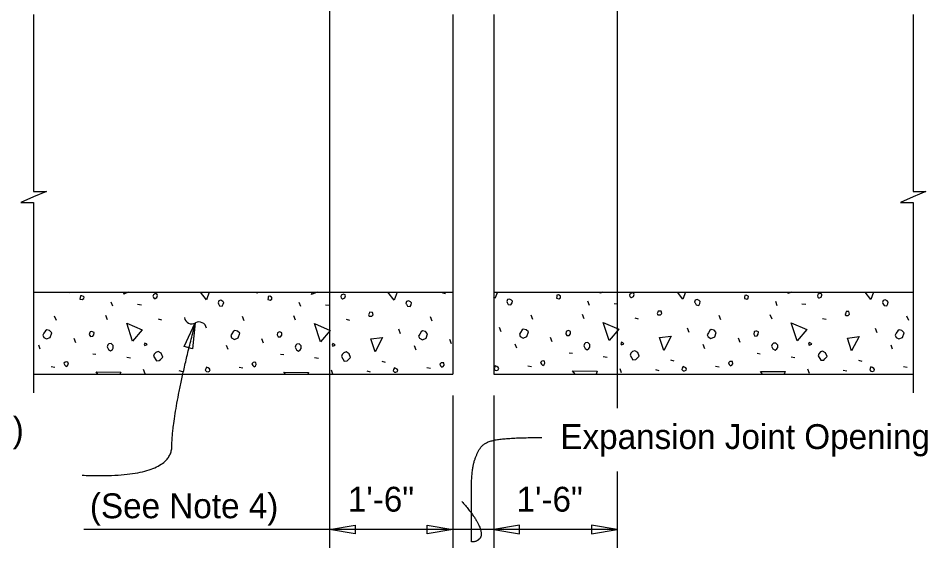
# Model space of a CAD drawing. Extents: x 0 to 41.1, y 0 to 25.9.
# Drawn here: x 23.59 to 30.96, y 12.63 to 16.93 of the extents above; entities that cross this region are included whole.
import ezdxf

# ---------------------------------------------------------------- set-up
doc = ezdxf.new("R2010")
doc.units = 0
for name, color, linetype in [('CL_Major', 7, 'Continuous'), ('Dimension', 7, 'Continuous'), ('Miscellaneous', 7, 'Continuous'), ('SupstrConc', 7, 'Continuous'), ('TextStructures', 7, 'Continuous')]:
    doc.layers.add(name, color=color, linetype=linetype)

msp = doc.modelspace()

# ---------------------------------------------------------------- linework, layer by layer
at = {"layer": 'CL_Major'}
for p, q in [((26.1118, 25.3255), (26.1118, 12.6331)), ((28.4451, 25.3255), (28.4451, 13.7657)), ((28.4451, 13.2526), (28.4451, 12.6331))]:
    msp.add_line(p, q, dxfattribs=at)
at = {"layer": 'Dimension'}
for p, q in [((27.1118, 13.8672), (27.1118, 12.6331)), ((27.4452, 13.8672), (27.4452, 12.6331)), ((28.4451, 12.7811), (26.1118, 12.7811))]:
    msp.add_line(p, q, dxfattribs=at)
for points in [[(23.712, 16.9573), (23.712, 15.5233), (23.8153, 15.5233), (23.712, 15.4783), (23.6086, 15.4333), (23.712, 15.4333), (23.712, 13.8908)], [(30.845, 16.9573), (30.845, 15.5233), (30.9484, 15.5233), (30.845, 15.4783), (30.7417, 15.4333), (30.845, 15.4333), (30.845, 13.8908)]]:
    msp.add_lwpolyline(points, dxfattribs=at)
for points in [[(25.0235, 14.4569), (25.0013, 14.2468), (24.9333, 14.2659)], [(26.1118, 12.7812), (26.3201, 12.8165), (26.3201, 12.746)], [(27.1118, 12.7812), (26.9036, 12.746), (26.9036, 12.8165)], [(27.4452, 12.7812), (27.6534, 12.746), (27.6534, 12.8165)], [(28.4452, 12.7812), (28.2369, 12.8165), (28.2369, 12.746)]]:
    msp.add_lwpolyline(points, close=True, dxfattribs=at)
for centre, start, end in [((24.9944, 14.508), 188.42943, 300.15665), ((25.0543, 14.4049), 8.42943, 120.15665)]:
    msp.add_arc(centre, 0.0596, start, end, dxfattribs=at)
for points in [[(24.107, 13.2213), (24.8329, 13.1916), (24.8345, 13.7279), (25.0236, 14.4567)], [(27.1848, 13.0096), (27.3029, 12.8733), (27.3543, 12.734), (27.3059, 12.6826), (27.2628, 12.6826), (27.2628, 12.6826), (27.2628, 12.9339), (27.2628, 13.2367), (27.2938, 13.373), (27.3664, 13.4972), (27.5995, 13.5274), (27.8326, 13.5274)]]:
    msp.add_open_spline(points, degree=2, dxfattribs=at)
at = {"layer": 'Miscellaneous'}
for p, q in [((23.9875, 14.7072), (24.0062, 14.7035)), ((25.5035, 14.7053), (25.53, 14.7)), ((27.0273, 14.7017), (27.0539, 14.6964)), ((29.3939, 14.7072), (29.395, 14.707)), ((24.3545, 14.5921), (24.3421, 14.6257)), ((24.5542, 14.608), (24.5861, 14.6045)), ((25.8783, 14.5886), (25.8659, 14.6222)), ((28.2194, 14.5992), (28.2071, 14.6328)), ((28.4192, 14.6151), (28.451, 14.6116)), ((29.7432, 14.5957), (29.7309, 14.6292)), ((29.943, 14.6116), (29.9748, 14.608)), ((26.0781, 14.6045), (26.1099, 14.601)), ((23.8966, 14.4772), (23.8825, 14.5126)), ((24.3121, 14.4825), (24.2979, 14.5179)), ((24.7222, 14.4896), (24.7505, 14.4825)), ((25.4204, 14.4737), (25.4063, 14.509)), ((25.8359, 14.479), (25.8217, 14.5143)), ((26.246, 14.4861), (26.2743, 14.479)), ((26.9443, 14.4701), (26.9301, 14.5055)), ((27.7616, 14.4843), (27.7474, 14.5196)), ((28.177, 14.4896), (28.1629, 14.5249)), ((28.5871, 14.4967), (28.6154, 14.4896)), ((29.2854, 14.4807), (29.2713, 14.5161)), ((29.7008, 14.4861), (29.6867, 14.5214)), ((30.1109, 14.4931), (30.1392, 14.4861)), ((30.8092, 14.4772), (30.7951, 14.5126)), ((26.6879, 14.3694), (26.6738, 14.4047)), ((27.5053, 14.3835), (27.4911, 14.4189)), ((29.0291, 14.38), (29.0149, 14.4153)), ((30.5529, 14.3765), (30.5387, 14.4118)), ((24.054, 14.2951), (24.0398, 14.3305)), ((25.5778, 14.2916), (25.5636, 14.327)), ((27.1016, 14.2881), (27.0874, 14.3234)), ((27.9189, 14.3022), (27.9048, 14.3376)), ((29.4427, 14.2987), (29.4286, 14.334)), ((23.7658, 14.2439), (23.7534, 14.2775)), ((25.2896, 14.2403), (25.2773, 14.2739)), ((26.8134, 14.2368), (26.8011, 14.2704)), ((27.6308, 14.2509), (27.6184, 14.2845)), ((29.1546, 14.2474), (29.1422, 14.281)), ((30.6784, 14.2439), (30.666, 14.2775)), ((24.1918, 14.2067), (24.2166, 14.2032)), ((24.4676, 14.1785), (24.4977, 14.1732)), ((25.7157, 14.2032), (25.7404, 14.1997)), ((25.9914, 14.1749), (26.0215, 14.1696)), ((28.0568, 14.2138), (28.0815, 14.2103)), ((28.3326, 14.1855), (28.3626, 14.1802)), ((29.5806, 14.2103), (29.6054, 14.2067)), ((29.8564, 14.182), (29.8864, 14.1767)), ((23.8542, 14.1024), (23.8843, 14.0971)), ((25.378, 14.0989), (25.4081, 14.0936)), ((26.5359, 14.1466), (26.5642, 14.1396)), ((26.9018, 14.0954), (26.9319, 14.0901)), ((27.7192, 14.1095), (27.7492, 14.1042)), ((28.877, 14.1572), (28.9053, 14.1502)), ((29.243, 14.106), (29.273, 14.1007)), ((30.4009, 14.1537), (30.4291, 14.1466)), ((30.7668, 14.1024), (30.7968, 14.0971)), ((24.6161, 14.0441), (24.6037, 14.0777)), ((24.8901, 14.0706), (24.9184, 14.0636)), ((26.1399, 14.0406), (26.1275, 14.0742)), ((26.4139, 14.0671), (26.4422, 14.06)), ((28.4811, 14.0512), (28.4687, 14.0848)), ((28.7551, 14.0777), (28.7833, 14.0706)), ((30.0049, 14.0476), (29.9925, 14.0812)), ((30.2789, 14.0742), (30.3072, 14.0671))]:
    msp.add_line(p, q, dxfattribs=at)
for points in [[(24.4429, 14.6911), (24.4478, 14.7072)], [(24.4788, 14.7072), (24.4429, 14.6911)], [(24.6904, 14.6558), (24.6974, 14.6558), (24.7116, 14.6628), (24.7169, 14.6787), (24.7151, 14.6876), (24.701, 14.6946), (24.6833, 14.684), (24.6797, 14.6734), (24.6833, 14.6628), (24.6904, 14.6558)], [(25.1129, 14.6434), (25.0643, 14.7072)], [(25.1367, 14.7072), (25.1129, 14.6434)], [(25.9667, 14.6876), (25.9727, 14.7072)], [(26.0105, 14.7072), (25.9667, 14.6876)], [(26.2142, 14.6522), (26.2212, 14.6522), (26.2354, 14.6593), (26.2407, 14.6752), (26.2389, 14.684), (26.2248, 14.6911), (26.2071, 14.6805), (26.2036, 14.6699), (26.2071, 14.6593), (26.2142, 14.6522)], [(26.6367, 14.6398), (26.5854, 14.7072)], [(26.6619, 14.7072), (26.6367, 14.6398)], [(27.4739, 14.7072), (27.454, 14.654)], [(27.9525, 14.6575), (27.9719, 14.6522), (27.9843, 14.6611), (27.9861, 14.6734), (27.9826, 14.677), (27.9684, 14.684), (27.956, 14.6823), (27.9543, 14.6699), (27.9525, 14.6575)], [(28.3078, 14.6982), (28.3106, 14.7072)], [(28.328, 14.7072), (28.3078, 14.6982)], [(28.5553, 14.6628), (28.5624, 14.6628), (28.5765, 14.6699), (28.5818, 14.6858), (28.5801, 14.6946), (28.5659, 14.7017), (28.5482, 14.6911), (28.5447, 14.6805), (28.5482, 14.6699), (28.5553, 14.6628)], [(28.9778, 14.6505), (28.9346, 14.7072)], [(28.999, 14.7072), (28.9778, 14.6505)], [(29.8316, 14.6946), (29.8355, 14.7072)], [(29.8597, 14.7072), (29.8316, 14.6946)], [(30.0791, 14.6593), (30.0862, 14.6593), (30.1003, 14.6664), (30.1056, 14.6823), (30.1039, 14.6911), (30.0897, 14.6982), (30.0721, 14.6876), (30.0685, 14.677), (30.0721, 14.6664), (30.0791, 14.6593)], [(30.5016, 14.6469), (30.4558, 14.7072)], [(30.5242, 14.7072), (30.5016, 14.6469)], [(24.0875, 14.6505), (24.107, 14.6452), (24.1194, 14.654), (24.1211, 14.6664), (24.1176, 14.6699), (24.1035, 14.677), (24.0911, 14.6752), (24.0893, 14.6628), (24.0875, 14.6505)], [(25.2118, 14.6116), (25.2207, 14.5957), (25.2419, 14.5921), (25.2507, 14.608), (25.2543, 14.6222), (25.2454, 14.631), (25.2295, 14.6398), (25.2136, 14.6345), (25.2083, 14.6186), (25.2118, 14.6116)], [(25.6114, 14.6469), (25.6308, 14.6416), (25.6432, 14.6505), (25.6449, 14.6628), (25.6414, 14.6664), (25.6273, 14.6734), (25.6149, 14.6717), (25.6131, 14.6593), (25.6114, 14.6469)], [(26.7357, 14.608), (26.7445, 14.5921), (26.7657, 14.5886), (26.7746, 14.6045), (26.7781, 14.6186), (26.7692, 14.6275), (26.7533, 14.6363), (26.7374, 14.631), (26.7321, 14.6151), (26.7357, 14.608)], [(27.454, 14.654), (27.4451, 14.6656)], [(27.553, 14.6222), (27.5618, 14.6063), (27.583, 14.6027), (27.5919, 14.6186), (27.5954, 14.6328), (27.5866, 14.6416), (27.5707, 14.6505), (27.5548, 14.6452), (27.5494, 14.6292), (27.553, 14.6222)], [(29.0768, 14.6186), (29.0856, 14.6027), (29.1069, 14.5992), (29.1157, 14.6151), (29.1192, 14.6292), (29.1104, 14.6381), (29.0945, 14.6469), (29.0786, 14.6416), (29.0733, 14.6257), (29.0768, 14.6186)], [(29.4763, 14.654), (29.4958, 14.6487), (29.5081, 14.6575), (29.5099, 14.6699), (29.5064, 14.6734), (29.4922, 14.6805), (29.4798, 14.6787), (29.4781, 14.6664), (29.4763, 14.654)], [(30.6006, 14.6151), (30.6095, 14.5992), (30.6307, 14.5957), (30.6395, 14.6116), (30.643, 14.6257), (30.6342, 14.6345), (30.6183, 14.6434), (30.6024, 14.6381), (30.5971, 14.6222), (30.6006, 14.6151)], [(26.4334, 14.5108), (26.4546, 14.5108), (26.4652, 14.5214), (26.4599, 14.5409), (26.4369, 14.5426), (26.4334, 14.532), (26.4281, 14.5232), (26.4334, 14.5108), (26.4298, 14.5143)], [(28.7745, 14.5214), (28.7957, 14.5214), (28.8063, 14.532), (28.801, 14.5515), (28.778, 14.5532), (28.7745, 14.5426), (28.7692, 14.5338), (28.7745, 14.5214), (28.771, 14.5249)], [(30.2983, 14.5179), (30.3195, 14.5179), (30.3301, 14.5285), (30.3248, 14.5479), (30.3019, 14.5497), (30.2983, 14.5391), (30.293, 14.5302), (30.2983, 14.5179), (30.2948, 14.5214)], [(28.3803, 14.3146), (28.3326, 14.4613), (28.4581, 14.4065), (28.3803, 14.3146)], [(23.7941, 14.3393), (23.8171, 14.327), (23.8471, 14.3393), (23.8595, 14.3765), (23.8418, 14.3941), (23.8188, 14.3994), (23.8082, 14.3924), (23.7959, 14.3729), (23.787, 14.357), (23.7941, 14.3393)], [(24.1636, 14.3623), (24.1724, 14.3464), (24.1918, 14.3482), (24.2007, 14.3605), (24.2025, 14.38), (24.1901, 14.3853), (24.1812, 14.3871), (24.1706, 14.3835), (24.1671, 14.38), (24.1636, 14.3623)], [(24.5153, 14.3075), (24.4676, 14.4542), (24.5931, 14.3994), (24.5153, 14.3075)], [(25.3179, 14.3358), (25.3409, 14.3234), (25.3709, 14.3358), (25.3833, 14.3729), (25.3656, 14.3906), (25.3427, 14.3959), (25.3321, 14.3888), (25.3197, 14.3694), (25.3108, 14.3535), (25.3179, 14.3358)], [(26.0392, 14.304), (25.9914, 14.4507), (26.1169, 14.3959), (26.0392, 14.304)], [(26.8417, 14.3323), (26.8647, 14.3199), (26.8948, 14.3323), (26.9071, 14.3694), (26.8895, 14.3871), (26.8665, 14.3924), (26.8559, 14.3853), (26.8435, 14.3658), (26.8347, 14.3499), (26.8417, 14.3323)], [(27.659, 14.3464), (27.682, 14.334), (27.7121, 14.3464), (27.7245, 14.3835), (27.7068, 14.4012), (27.6838, 14.4065), (27.6732, 14.3994), (27.6608, 14.38), (27.652, 14.3641), (27.659, 14.3464)], [(28.0285, 14.3694), (28.0374, 14.3535), (28.0568, 14.3552), (28.0656, 14.3676), (28.0674, 14.3871), (28.055, 14.3924), (28.0462, 14.3941), (28.0356, 14.3906), (28.032, 14.3871), (28.0285, 14.3694)], [(29.1829, 14.3429), (29.2058, 14.3305), (29.2359, 14.3429), (29.2483, 14.38), (29.2306, 14.3977), (29.2076, 14.403), (29.197, 14.3959), (29.1846, 14.3765), (29.1758, 14.3605), (29.1829, 14.3429)], [(29.5523, 14.3658), (29.5612, 14.3499), (29.5806, 14.3517), (29.5895, 14.3641), (29.5912, 14.3835), (29.5788, 14.3888), (29.57, 14.3906), (29.5594, 14.3871), (29.5559, 14.3835), (29.5523, 14.3658)], [(29.9041, 14.311), (29.8564, 14.4578), (29.9819, 14.403), (29.9041, 14.311)], [(30.7067, 14.3393), (30.7297, 14.327), (30.7597, 14.3393), (30.7721, 14.3765), (30.7544, 14.3941), (30.7314, 14.3994), (30.7208, 14.3924), (30.7084, 14.3729), (30.6996, 14.357), (30.7067, 14.3393)], [(25.6874, 14.3588), (25.6962, 14.3429), (25.7157, 14.3446), (25.7245, 14.357), (25.7263, 14.3765), (25.7139, 14.3818), (25.7051, 14.3835), (25.6944, 14.38), (25.6909, 14.3765), (25.6874, 14.3588)], [(26.4811, 14.2227), (26.4475, 14.327), (26.5412, 14.3393), (26.4811, 14.2227)], [(28.8222, 14.2333), (28.7887, 14.3376), (28.8823, 14.3499), (28.8222, 14.2333)], [(30.3461, 14.2297), (30.3125, 14.334), (30.4062, 14.3464), (30.3461, 14.2297)], [(24.3085, 14.2633), (24.3191, 14.2421), (24.3368, 14.2315), (24.3509, 14.2421), (24.358, 14.2527), (24.358, 14.2739), (24.3421, 14.2898), (24.3227, 14.2881), (24.3138, 14.2792), (24.3085, 14.2633)], [(24.6143, 14.2722), (24.6338, 14.281), (24.6267, 14.2881), (24.6143, 14.2934), (24.609, 14.281), (24.6143, 14.2722)], [(25.8323, 14.2598), (25.8429, 14.2386), (25.8606, 14.228), (25.8748, 14.2386), (25.8818, 14.2492), (25.8818, 14.2704), (25.8659, 14.2863), (25.8465, 14.2845), (25.8376, 14.2757), (25.8323, 14.2598)], [(26.1382, 14.2686), (26.1576, 14.2775), (26.1505, 14.2845), (26.1382, 14.2898), (26.1329, 14.2775), (26.1382, 14.2686)], [(28.1735, 14.2704), (28.1841, 14.2492), (28.2018, 14.2386), (28.2159, 14.2492), (28.223, 14.2598), (28.223, 14.281), (28.2071, 14.2969), (28.1876, 14.2951), (28.1788, 14.2863), (28.1735, 14.2704)], [(28.4793, 14.2792), (28.4987, 14.2881), (28.4917, 14.2951), (28.4793, 14.3004), (28.474, 14.2881), (28.4793, 14.2792)], [(29.6973, 14.2668), (29.7079, 14.2456), (29.7256, 14.235), (29.7397, 14.2456), (29.7468, 14.2562), (29.7468, 14.2775), (29.7309, 14.2934), (29.7114, 14.2916), (29.7026, 14.2828), (29.6973, 14.2668)], [(30.0031, 14.2757), (30.0226, 14.2845), (30.0155, 14.2916), (30.0031, 14.2969), (29.9978, 14.2845), (30.0031, 14.2757)], [(24.6851, 14.1873), (24.708, 14.1502), (24.731, 14.1519), (24.7399, 14.1608), (24.7593, 14.1802), (24.7469, 14.2103), (24.7222, 14.2244), (24.7045, 14.2174), (24.6904, 14.2032), (24.6851, 14.1873)], [(26.2089, 14.1838), (26.2318, 14.1466), (26.2548, 14.1484), (26.2637, 14.1572), (26.2831, 14.1767), (26.2707, 14.2067), (26.246, 14.2209), (26.2283, 14.2138), (26.2142, 14.1997), (26.2089, 14.1838)], [(28.55, 14.1944), (28.573, 14.1572), (28.596, 14.159), (28.6048, 14.1679), (28.6242, 14.1873), (28.6119, 14.2174), (28.5871, 14.2315), (28.5694, 14.2244), (28.5553, 14.2103), (28.55, 14.1944)], [(30.0738, 14.1908), (30.0968, 14.1537), (30.1198, 14.1555), (30.1286, 14.1643), (30.1481, 14.1838), (30.1357, 14.2138), (30.1109, 14.228), (30.0933, 14.2209), (30.0791, 14.2067), (30.0738, 14.1908)], [(23.9656, 14.1148), (23.9762, 14.1042), (23.9868, 14.1113), (23.9939, 14.1219), (23.9903, 14.1396), (23.9815, 14.1413), (23.9691, 14.1396), (23.9585, 14.129), (23.9656, 14.1148)], [(25.1146, 14.0618), (25.127, 14.06), (25.1394, 14.0653), (25.1429, 14.0759), (25.1376, 14.0848), (25.127, 14.0918), (25.1146, 14.0971), (25.1075, 14.083), (25.104, 14.0724), (25.1146, 14.0618)], [(25.4894, 14.1113), (25.5, 14.1007), (25.5106, 14.1077), (25.5177, 14.1184), (25.5141, 14.136), (25.5053, 14.1378), (25.4929, 14.136), (25.4823, 14.1254), (25.4894, 14.1113)], [(26.6384, 14.0583), (26.6508, 14.0565), (26.6632, 14.0618), (26.6667, 14.0724), (26.6614, 14.0812), (26.6508, 14.0883), (26.6384, 14.0936), (26.6314, 14.0795), (26.6278, 14.0689), (26.6384, 14.0583)], [(27.0132, 14.1077), (27.0238, 14.0971), (27.0344, 14.1042), (27.0415, 14.1148), (27.0379, 14.1325), (27.0291, 14.1343), (27.0167, 14.1325), (27.0061, 14.1219), (27.0132, 14.1077)], [(27.4558, 14.0724), (27.4681, 14.0706), (27.4805, 14.0759), (27.484, 14.0865), (27.4787, 14.0954), (27.4681, 14.1024), (27.4558, 14.1077), (27.4487, 14.0936), (27.4451, 14.083), (27.4558, 14.0724)], [(27.8305, 14.1219), (27.8411, 14.1113), (27.8517, 14.1184), (27.8588, 14.129), (27.8553, 14.1466), (27.8464, 14.1484), (27.8341, 14.1466), (27.8235, 14.136), (27.8305, 14.1219)], [(28.9796, 14.0689), (28.9919, 14.0671), (29.0043, 14.0724), (29.0079, 14.083), (29.0026, 14.0918), (28.9919, 14.0989), (28.9796, 14.1042), (28.9725, 14.0901), (28.969, 14.0795), (28.9796, 14.0689)], [(29.3543, 14.1184), (29.3649, 14.1077), (29.3756, 14.1148), (29.3826, 14.1254), (29.3791, 14.1431), (29.3702, 14.1449), (29.3579, 14.1431), (29.3473, 14.1325), (29.3543, 14.1184)], [(30.5034, 14.0653), (30.5158, 14.0636), (30.5281, 14.0689), (30.5317, 14.0795), (30.5264, 14.0883), (30.5158, 14.0954), (30.5034, 14.1007), (30.4963, 14.0865), (30.4928, 14.0759), (30.5034, 14.0653)], [(24.2331, 14.0406), (24.2184, 14.06), (24.4181, 14.0583), (24.4115, 14.0406)], [(25.7543, 14.0406), (25.7422, 14.0565), (25.9419, 14.0547), (25.9366, 14.0406)], [(28.1035, 14.0406), (28.0833, 14.0671), (28.2831, 14.0653), (28.2738, 14.0406)], [(29.6246, 14.0406), (29.6071, 14.0636), (29.8069, 14.0618), (29.799, 14.0406)]]:
    msp.add_lwpolyline(points, dxfattribs=at)
at = {"layer": 'SupstrConc'}
for p, q in [((27.1118, 16.9573), (27.1118, 14.0406)), ((27.4451, 16.9573), (27.4451, 14.0406)), ((23.712, 14.7072), (27.1118, 14.7072)), ((27.4451, 14.7072), (30.845, 14.7072)), ((23.712, 14.0406), (27.1118, 14.0406)), ((27.4451, 14.0406), (30.845, 14.0406))]:
    msp.add_line(p, q, dxfattribs=at)
at = {"layer": 'TextStructures'}
msp.add_line((26.1118, 12.7812), (24.1193, 12.7812), dxfattribs=at)

# ---------------------------------------------------------------- texts
at = {"layer": 'Dimension'}
msp.add_text('Bridge Deck (shown)', height=0.2016, dxfattribs=at).set_placement((21.1302, 13.4931))
at = {"layer": 'TextStructures'}
for s, p in [('Expansion Joint Opening', (27.9841, 13.4341)), ('(See Note 4)', (24.1684, 12.8728)), ('1\'-6"', (26.2611, 12.9264)), ('1\'-6"', (27.6293, 12.9264))]:
    msp.add_text(s, height=0.2016, dxfattribs=at).set_placement(p)

doc.saveas('drawing.dxf')
